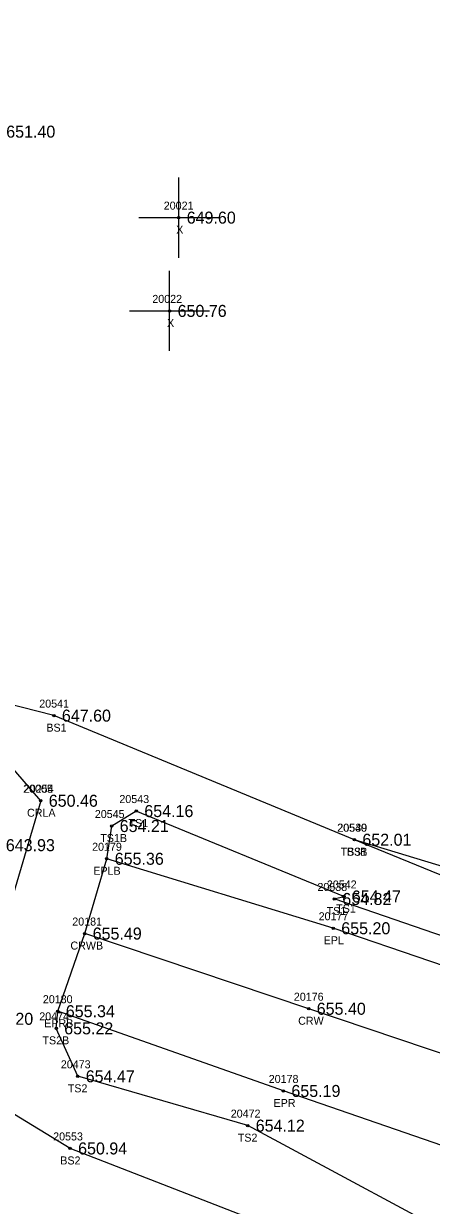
# Model space of a CAD drawing. Extents: x 1655675 to 1657082, y 1004080 to 1005193.
# Drawn here: x 1656393.9 to 1656444.9, y 1004582.5 to 1004730.1 of the extents above; entities that cross this region are included whole.
import ezdxf

# ---------------------------------------------------------------- set-up
doc = ezdxf.new("R2010")
doc.units = 0
for name, color, linetype in [('RD_DTM_BkLn1', 7, 'Continuous'), ('RD_DTM_BkLn2', 7, 'Continuous'), ('RD_DTM_BkLn_txCode', 7, 'Continuous'), ('RD_EX_H2O', 7, 'Continuous'), ('RD_EX_H2O_txCode', 7, 'Continuous'), ('RD_EX_Misc', 7, 'Continuous'), ('RD_EX_Misc_txCode', 7, 'Continuous'), ('RD_EX_Road', 7, 'Continuous'), ('RD_EX_Road_txCode', 7, 'Continuous'), ('RD_EX_TX_H2O_ELEV', 7, 'Continuous'), ('RD_EX_TX_Misc_ELEV', 7, 'Continuous'), ('RD_EX_TX_Road_ELEV', 7, 'Continuous'), ('RD_HC_Survey_ELEV', 7, 'Continuous'), ('RD_HC_Survey_txCode', 7, 'Continuous'), ('RD_SMD_Locator', 7, 'Continuous')]:
    doc.layers.add(name, color=color, linetype=linetype)

msp = doc.modelspace()

# ---------------------------------------------------------------- linework, layer by layer
at = {"layer": 'RD_DTM_BkLn1'}
for points in [[(1656398.02, 1004604.64), (1656398.22, 1004606.78), (1656401.58, 1004616.48), (1656404.34, 1004625.82), (1656404.96, 1004629.91)], [(1657061.44, 1004399.53), (1657012.07, 1004414.01), (1656963.11, 1004429.39), (1656914.21, 1004444.93), (1656865.73, 1004460.97), (1656817.07, 1004476.94), (1656768.62, 1004493.15), (1656720.24, 1004509.39), (1656671.72, 1004525.86), (1656623.45, 1004542.51), (1656574.61, 1004558.72), (1656526.43, 1004574.41), (1656478.09, 1004590.75), (1656429.6, 1004607.09), (1656401.58, 1004616.48)]]:
    msp.add_lwpolyline(points, dxfattribs=at)
at = {"layer": 'RD_DTM_BkLn2'}
msp.add_line((1656495.21, 1004610.01), (1656435.31, 1004628.2), dxfattribs=at)
for points in [[(1656540.84, 1004587.48), (1656491.44, 1004605.3), (1656435.31, 1004628.2), (1656397.73, 1004643.7), (1656383.79, 1004647.24)], [(1656543.75, 1004590.98), (1656541.14, 1004585.84), (1656537.31, 1004584.99), (1656490.63, 1004600.92), (1656432.8, 1004620.8), (1656433.99, 1004621.11), (1656408.04, 1004631.78), (1656404.96, 1004629.91)], [(1656526.96, 1004552.22), (1656473.05, 1004574.77), (1656453.3, 1004575.67), (1656421.97, 1004592.49), (1656400.71, 1004598.65), (1656398.02, 1004604.64)], [(1656501.89, 1004508.05), (1656515.57, 1004543.15), (1656505.12, 1004553.79), (1656467.3, 1004566.38), (1656447.68, 1004569.18), (1656425.18, 1004579.78), (1656399.76, 1004589.64), (1656384.32, 1004599.06)]]:
    msp.add_lwpolyline(points, dxfattribs=at)
at = {"layer": 'RD_EX_H2O'}
for points in [[(1656396.09, 1004633.07), (1656383.79, 1004647.24), (1656376.78, 1004660.97), (1656381.31, 1004695.03), (1656390.77, 1004716.64), (1656386.6, 1004756.66), (1656392.47, 1004790.44), (1656395.46, 1004834.73), (1656418.17, 1004880.53), (1656428.48, 1004936.46), (1656416.99, 1004968.14), (1656420.24, 1005011.82), (1656412.2, 1005039.74), (1656428.37, 1005086.9), (1656442.1, 1005137.22), (1656437.49, 1005175.75)], [(1656396.09, 1004633.07), (1656388.01, 1004605.83), (1656383, 1004600.69), (1656372.14, 1004591.42), (1656381.32, 1004569.61), (1656373.51, 1004535.02), (1656369.64, 1004512.2), (1656394.86, 1004499.5), (1656391.61, 1004464.63), (1656362.04, 1004437.06), (1656349.14, 1004389.09), (1656389.79, 1004361.99), (1656392.68, 1004307.58), (1656360.76, 1004281.14), (1656349.55, 1004259.28), (1656348.46, 1004221.09), (1656343.48, 1004177.61), (1656328.72, 1004142.77), (1656319.4, 1004085.87)]]:
    msp.add_lwpolyline(points, dxfattribs=at)
at = {"layer": 'RD_EX_Misc'}
for p, q in [((1656413.34, 1004700.9), (1656413.34, 1004710.9)), ((1656408.34, 1004705.9), (1656418.34, 1004705.9)), ((1656412.2, 1004689.25), (1656412.2, 1004699.25)), ((1656407.2, 1004694.25), (1656417.2, 1004694.25))]:
    msp.add_line(p, q, dxfattribs=at)
at = {"layer": 'RD_EX_Road'}
for points in [[(1657064.39, 1004409.09), (1657015.67, 1004424.64), (1656965.82, 1004440.6), (1656917.99, 1004455.95), (1656868.5, 1004471.86), (1656826.53, 1004486.06), (1656801.74, 1004494.51), (1656772.14, 1004504.27), (1656723.45, 1004520.92), (1656674.94, 1004537.34), (1656626.5, 1004553.88), (1656578.27, 1004569.52), (1656529.18, 1004584.75), (1656481.5, 1004600.51), (1656432.67, 1004617.14), (1656404.34, 1004625.82)], [(1657057.77, 1004388.92), (1657009.7, 1004404.08), (1656958.18, 1004419.84), (1656956.49, 1004419.67), (1656924.83, 1004429.55), (1656916.51, 1004432.8), (1656911.19, 1004434.68), (1656862.46, 1004450.21), (1656813.53, 1004466.42), (1656765.51, 1004482.33), (1656716.81, 1004499.14), (1656668.6, 1004515.93), (1656620.24, 1004532.54), (1656571.72, 1004548.37), (1656523.3, 1004563.77), (1656474.37, 1004580.29), (1656426.43, 1004596.82), (1656398.22, 1004606.78)]]:
    msp.add_lwpolyline(points, dxfattribs=at)
at = {"layer": 'RD_SMD_Locator'}
for centre in [(1656413.34, 1004705.9), (1656412.2, 1004694.25), (1656397.73, 1004643.7), (1656396.09, 1004633.07), (1656396.09, 1004633.07), (1656408.04, 1004631.78), (1656404.96, 1004629.91), (1656435.31, 1004628.2), (1656435.31, 1004628.2), (1656404.34, 1004625.82), (1656432.8, 1004620.8), (1656433.99, 1004621.11), (1656401.58, 1004616.48), (1656432.67, 1004617.14), (1656398.22, 1004606.78), (1656429.6, 1004607.09), (1656398.02, 1004604.64), (1656400.71, 1004598.65), (1656426.43, 1004596.82), (1656421.97, 1004592.49), (1656399.76, 1004589.64)]:
    msp.add_circle(centre, 0.15, dxfattribs=at)

# ---------------------------------------------------------------- texts
at = {"layer": 'RD_DTM_BkLn_txCode'}
for s, p in [('20541', (1656395.9, 1004644.7)), ('BS1', (1656396.79, 1004641.7)), ('20543', (1656405.92, 1004632.78)), ('20545', (1656402.85, 1004630.91)), ('TS1', (1656407.07, 1004629.78)), ('20540', (1656433.15, 1004629.2)), ('20539', (1656433.19, 1004629.2)), ('TS1B', (1656403.53, 1004627.91)), ('TS3B', (1656433.59, 1004626.2)), ('BS1', (1656434.36, 1004626.2)), ('20538', (1656430.69, 1004621.8)), ('20542', (1656431.87, 1004622.11)), ('TS1', (1656431.84, 1004618.8)), ('TS1', (1656433.03, 1004619.11)), ('20474', (1656395.9, 1004605.64)), ('TS2B', (1656396.3, 1004602.64)), ('20473', (1656398.6, 1004599.65)), ('TS2', (1656399.47, 1004596.65)), ('20472', (1656419.85, 1004593.49)), ('20553', (1656397.64, 1004590.64)), ('TS2', (1656420.73, 1004590.49)), ('BS2', (1656398.53, 1004587.64))]:
    msp.add_text(s, height=1, dxfattribs=at).set_placement(p)
at = {"layer": 'RD_EX_H2O_txCode'}
for s, p in [('20005', (1656393.89, 1004634.07)), ('20254', (1656393.97, 1004634.07)), ('CRLA', (1656394.37, 1004631.07)), ('CRLA', (1656394.37, 1004631.07))]:
    msp.add_text(s, height=1, dxfattribs=at).set_placement(p)
at = {"layer": 'RD_EX_Misc_txCode'}
for s, p in [('20021', (1656411.47, 1004706.9)), ('X', (1656413.03, 1004703.9)), ('20022', (1656410.04, 1004695.25)), ('X', (1656411.88, 1004692.25))]:
    msp.add_text(s, height=1, dxfattribs=at).set_placement(p)
at = {"layer": 'RD_EX_Road_txCode'}
for s, p in [('20179', (1656402.51, 1004626.82)), ('EPLB', (1656402.66, 1004623.82)), ('20177', (1656430.84, 1004618.14)), ('EPL', (1656431.47, 1004615.14)), ('20180', (1656396.35, 1004607.78)), ('EPRB', (1656396.52, 1004604.78)), ('20178', (1656424.6, 1004597.82)), ('EPR', (1656425.2, 1004594.82))]:
    msp.add_text(s, height=1, dxfattribs=at).set_placement(p)
at = {"layer": 'RD_EX_TX_H2O_ELEV'}
for s, p in [('651.40', (1656391.77, 1004715.89)), ('650.46', (1656397.09, 1004632.32)), ('650.46', (1656397.09, 1004632.32)), ('650.20', (1656389.01, 1004605.08))]:
    msp.add_text(s, height=1.5, dxfattribs=at).set_placement(p)
at = {"layer": 'RD_EX_TX_Misc_ELEV'}
for s, p in [('649.60', (1656414.34, 1004705.15)), ('650.76', (1656413.2, 1004693.5)), ('647.60', (1656398.73, 1004642.95)), ('654.16', (1656409.04, 1004631.03)), ('654.21', (1656405.96, 1004629.16)), ('643.93', (1656391.72, 1004626.77)), ('643.93', (1656391.72, 1004626.77)), ('652.01', (1656436.31, 1004627.45)), ('652.01', (1656436.31, 1004627.45)), ('654.82', (1656433.8, 1004620.05)), ('654.47', (1656434.99, 1004620.36)), ('655.22', (1656399.02, 1004603.89)), ('654.47', (1656401.71, 1004597.9)), ('654.12', (1656422.97, 1004591.74)), ('650.94', (1656400.76, 1004588.89))]:
    msp.add_text(s, height=1.5, dxfattribs=at).set_placement(p)
at = {"layer": 'RD_EX_TX_Road_ELEV'}
for s, p in [('655.36', (1656405.34, 1004625.07)), ('655.20', (1656433.67, 1004616.39)), ('655.34', (1656399.22, 1004606.03)), ('655.19', (1656427.43, 1004596.07))]:
    msp.add_text(s, height=1.5, dxfattribs=at).set_placement(p)
at = {"layer": 'RD_HC_Survey_ELEV'}
for s, p in [('655.49', (1656402.58, 1004615.73)), ('655.40', (1656430.6, 1004606.34))]:
    msp.add_text(s, height=1.5, dxfattribs=at).set_placement(p)
at = {"layer": 'RD_HC_Survey_txCode'}
for s, p in [('20181', (1656400.03, 1004617.48)), ('CRWB', (1656399.8, 1004614.48)), ('20176', (1656427.74, 1004608.09)), ('CRW', (1656428.28, 1004605.09))]:
    msp.add_text(s, height=1, dxfattribs=at).set_placement(p)

doc.saveas('drawing.dxf')
